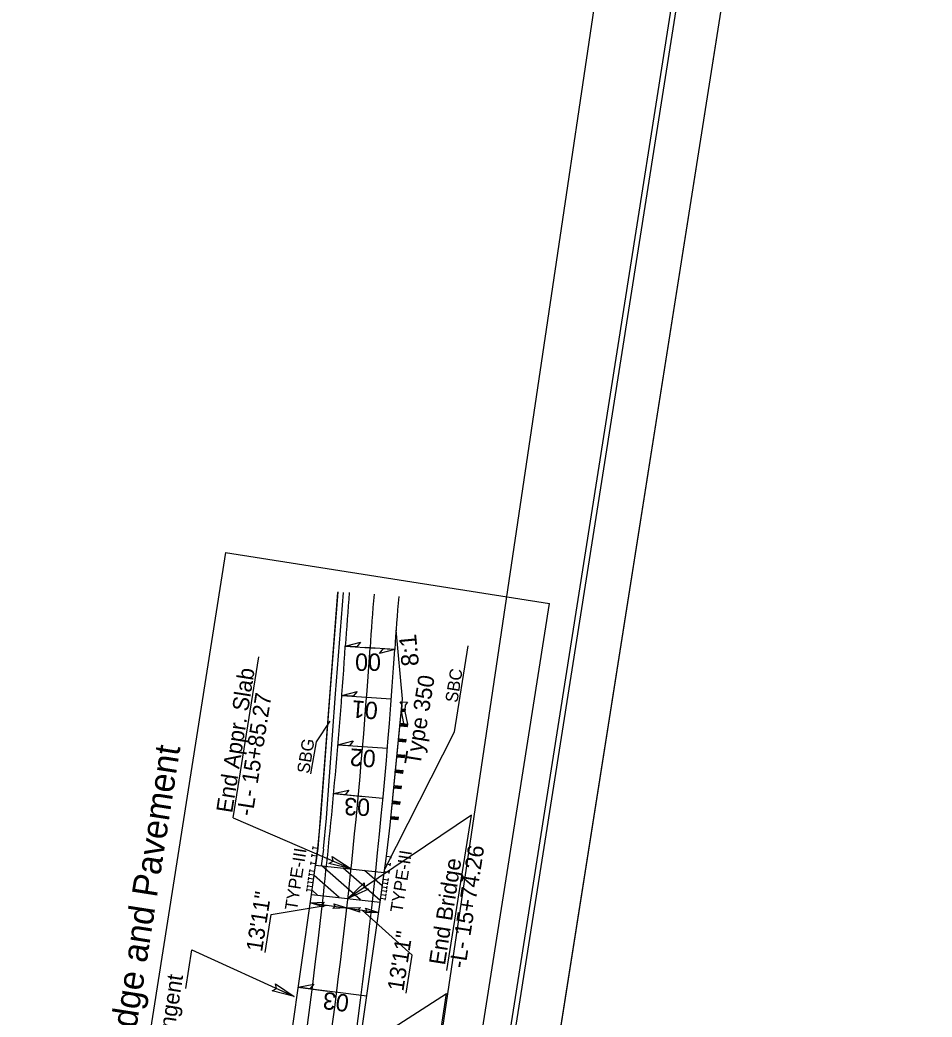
# Model space of a CAD drawing. Extents: x 1698669 to 1700017, y 707624 to 709955.
# Drawn here: x 1699557 to 1700017, y 708286 to 708790 of the extents above; entities that cross this region are included whole.
import ezdxf

# ---------------------------------------------------------------- set-up
doc = ezdxf.new("R2010")
doc.units = 0
for name, color, linetype in [('Prop Approach Slab', 7, 'Continuous'), ('Prop Approach Slab Hatching', 7, 'Continuous'), ('Prop Conc Shoulder Berm Gutter', 7, 'Continuous'), ('Prop Dimension', 7, 'Continuous'), ('Prop EOT', 7, 'Continuous'), ('Prop Guardrail', 7, 'Continuous'), ('Prop Guardrail Anchor Unit CELL', 7, 'Continuous'), ('Prop Horizontal Alignment', 7, 'Continuous'), ('Prop Paved Shoulder', 7, 'Continuous'), ('Prop Roadway Bridge', 7, 'Continuous'), ('Prop Structure Anchor Unit CELL', 7, 'Continuous'), ('Prop Superelevation  Arrow CELL', 7, 'Continuous'), ('Prop Superelevation Label', 7, 'Continuous'), ('Prop Terminator CELL', 7, 'Continuous'), ('Sheet Border Standard 30in CELL', 7, 'Continuous'), ('Sheet Clip Boundary CELL', 7, 'Continuous'), ('Sheet Cutting Line CELL', 7, 'Continuous'), ('Sheet Plot Border Inside CELL', 7, 'Continuous'), ('Sheet Plot Border Outside CELL', 7, 'Continuous')]:
    doc.layers.add(name, color=color, linetype=linetype)

msp = doc.modelspace()

# ---------------------------------------------------------------- linework, layer by layer
at = {"layer": 'Prop Approach Slab'}
for p, q in [((1699704.32, 708348.27), (1699706.42, 708363.04)), ((1699738.92, 708344.44), (1699741.04, 708359.38))]:
    msp.add_line(p, q, dxfattribs=at)
at = {"layer": 'Prop Approach Slab Hatching'}
for p, q in [((1699729.14, 708345.52), (1699709.52, 708362.71)), ((1699739.02, 708345.18), (1699720.31, 708361.57)), ((1699718.29, 708346.72), (1699705.67, 708357.78)), ((1699740.07, 708352.57), (1699731.09, 708360.43)), ((1699707.43, 708347.93), (1699704.62, 708350.39))]:
    msp.add_line(p, q, dxfattribs=at)
at = {"layer": 'Prop Conc Shoulder Berm Gutter'}
for p, q in [((1699713.71, 708449.74), (1699717.72, 708500.9)), ((1699709.06, 708387.08), (1699713.71, 708449.74)), ((1699707.61, 708371.48), (1699709.06, 708387.08)), ((1699707.61, 708371.48), (1699706.42, 708363.04)), ((1699741.04, 708359.38), (1699741.49, 708362.58))]:
    msp.add_line(p, q, dxfattribs=at)
at = {"layer": 'Prop Dimension'}
for p, q in [((1699776.52, 708430.34), (1699783.37, 708473.73)), ((1699664.9, 708386.89), (1699677.7, 708468.16)), ((1699706.82, 708425.3), (1699713.71, 708435.77)), ((1699741.29, 708360.98), (1699776.52, 708430.34)), ((1699703.98, 708409.06), (1699706.82, 708425.3)), ((1699664.9, 708386.89), (1699724.29, 708361.15)), ((1699785.02, 708388.28), (1699722.68, 708346.24)), ((1699772.67, 708309.84), (1699785.02, 708388.28)), ((1699684, 708338.22), (1699712.17, 708342.86)), ((1699703.73, 708344.06), (1699738.17, 708339.18)), ((1699680.98, 708318.99), (1699684, 708338.22)), ((1699755.18, 708317.69), (1699729.98, 708340.34)), ((1699640.89, 708300.84), (1699643.95, 708320.3)), ((1699643.95, 708320.3), (1699695.65, 708296.84)), ((1699752.15, 708298.46), (1699755.18, 708317.69)), ((1699711.72, 708259.43), (1699772.5, 708298.31)), ((1699763.45, 708240.74), (1699772.5, 708298.31))]:
    msp.add_line(p, q, dxfattribs=at)
at = {"layer": 'Prop EOT'}
for centre, radius, start, end in [((1701480.04, 708357.02), 1762.5, 175.32699, 176.20849), ((1701480.04, 708357.02), 1737.5, 175.32699, 176.20849), ((1696875.02, 708661), 2852.55, 353.61848, 356.23256), ((1696865.17, 708662.86), 2887.5, 350.26654, 356.20849), ((1696875.02, 708661), 2852.55, 346.9592, 353.61848)]:
    msp.add_arc(centre, radius, start, end, dxfattribs=at)
at = {"layer": 'Prop Guardrail'}
for p, q in [((1699717.47, 708500.55), (1699707.61, 708371.48)), ((1699742.21, 708367.64), (1699743.98, 708383.22))]:
    msp.add_line(p, q, dxfattribs=at)
at = {"layer": 'Prop Guardrail Anchor Unit CELL'}
for p, q in [((1699743.98, 708383.22), (1699749.76, 708441.37)), ((1699750.07, 708443.95), (1699749.12, 708445.5)), ((1699749.12, 708445.5), (1699752.78, 708445.21)), ((1699751.69, 708441.8), (1699749.7, 708440.75)), ((1699749.83, 708441.99), (1699751.69, 708441.8)), ((1699749.83, 708441.99), (1699751.57, 708440.56)), ((1699749.86, 708441.4), (1699750.07, 708443.95)), ((1699750.62, 708441.34), (1699749.86, 708441.4)), ((1699751.38, 708441.27), (1699750.62, 708441.34)), ((1699751.59, 708443.82), (1699751.38, 708441.27)), ((1699751.57, 708440.56), (1699751.69, 708441.8)), ((1699751.57, 708440.56), (1699751.63, 708441.18)), ((1699752.78, 708445.21), (1699751.59, 708443.82)), ((1699749.7, 708440.75), (1699751.57, 708440.56)), ((1699751, 708434.46), (1699749.7, 708440.75)), ((1699752.91, 708434.27), (1699751.57, 708440.56)), ((1699748.97, 708433.41), (1699751, 708434.46)), ((1699748.97, 708433.41), (1699752.78, 708433.03)), ((1699749.1, 708434.65), (1699752.91, 708434.27)), ((1699750.88, 708433.22), (1699749.1, 708434.65)), ((1699750.88, 708433.22), (1699751, 708434.46)), ((1699752.91, 708434.27), (1699750.88, 708433.22)), ((1699751, 708434.46), (1699752.78, 708433.03)), ((1699752.78, 708433.03), (1699752.91, 708434.27)), ((1699748.19, 708425.57), (1699750.18, 708426.63)), ((1699748.32, 708426.81), (1699752.05, 708426.44)), ((1699750.06, 708425.38), (1699748.32, 708426.81)), ((1699750.06, 708425.38), (1699750.18, 708426.63)), ((1699752.05, 708426.44), (1699750.06, 708425.38)), ((1699750.18, 708426.63), (1699751.92, 708425.2)), ((1699751.92, 708425.2), (1699752.05, 708426.44)), ((1699748.19, 708425.57), (1699751.92, 708425.2)), ((1699747.41, 708417.73), (1699749.49, 708418.78)), ((1699747.41, 708417.73), (1699751.31, 708417.34)), ((1699747.54, 708418.97), (1699751.44, 708418.59)), ((1699749.36, 708417.54), (1699747.54, 708418.97)), ((1699749.36, 708417.54), (1699749.49, 708418.78)), ((1699751.44, 708418.59), (1699749.36, 708417.54)), ((1699749.49, 708418.78), (1699751.31, 708417.34)), ((1699751.31, 708417.34), (1699751.44, 708418.59)), ((1699746.63, 708409.89), (1699746.76, 708411.14)), ((1699746.76, 708411.14), (1699750.53, 708410.76)), ((1699748.52, 708409.7), (1699746.76, 708411.14)), ((1699746.63, 708409.89), (1699748.64, 708410.95)), ((1699746.63, 708409.89), (1699750.41, 708409.52)), ((1699748.52, 708409.7), (1699748.64, 708410.95)), ((1699750.53, 708410.76), (1699748.52, 708409.7)), ((1699748.64, 708410.95), (1699750.41, 708409.52)), ((1699750.41, 708409.52), (1699750.53, 708410.76)), ((1699745.85, 708402.05), (1699747.87, 708403.11)), ((1699745.85, 708402.05), (1699749.64, 708401.68)), ((1699745.98, 708403.3), (1699749.77, 708402.92)), ((1699747.75, 708401.87), (1699745.98, 708403.3)), ((1699747.75, 708401.87), (1699747.87, 708403.11)), ((1699749.77, 708402.92), (1699747.75, 708401.87)), ((1699747.87, 708403.11), (1699749.64, 708401.68)), ((1699749.64, 708401.68), (1699749.77, 708402.92)), ((1699745.07, 708394.22), (1699747.09, 708395.27)), ((1699745.07, 708394.22), (1699748.87, 708393.84)), ((1699745.2, 708395.46), (1699748.99, 708395.08)), ((1699746.97, 708394.03), (1699745.2, 708395.46)), ((1699746.97, 708394.03), (1699747.09, 708395.27)), ((1699748.99, 708395.08), (1699746.97, 708394.03)), ((1699747.09, 708395.27), (1699748.87, 708393.84)), ((1699748.87, 708393.84), (1699748.99, 708395.08)), ((1699744.29, 708386.38), (1699744.42, 708387.62)), ((1699746.28, 708387.44), (1699744.29, 708386.38)), ((1699744.29, 708386.38), (1699748.02, 708386.01)), ((1699744.42, 708387.62), (1699748.15, 708387.25)), ((1699744.42, 708387.62), (1699746.28, 708387.44)), ((1699746.16, 708386.19), (1699744.42, 708387.62)), ((1699746.16, 708386.19), (1699746.28, 708387.44)), ((1699748.15, 708387.25), (1699746.16, 708386.19)), ((1699746.28, 708387.44), (1699748.02, 708386.01)), ((1699748.02, 708386.01), (1699748.15, 708387.25))]:
    msp.add_line(p, q, dxfattribs=at)
at = {"layer": 'Prop Horizontal Alignment'}
for p, q in [((1699660.94, 708520.75), (1699581.95, 708018.92)), ((1699660.94, 708520.75), (1699824.35, 708495.03)), ((1699745.36, 707993.2), (1699824.35, 708495.03))]:
    msp.add_line(p, q, dxfattribs=at)
for centre, radius, start, end in [((1701492.52, 708356.2), 1762.5, 175.32699, 176.20849), ((1696865.17, 708662.86), 2875, 346.96755, 356.20849)]:
    msp.add_arc(centre, radius, start, end, dxfattribs=at)
at = {"layer": 'Prop Paved Shoulder'}
for p, q in [((1699716.51, 708449.52), (1699720.51, 708500.68)), ((1699750.32, 708446.96), (1699747.02, 708481.61)), ((1699711.86, 708386.88), (1699716.51, 708449.54)), ((1699743.98, 708383.22), (1699750.32, 708446.96)), ((1699710.4, 708371.22), (1699711.85, 708386.82)), ((1699742.21, 708367.64), (1699743.98, 708383.22)), ((1699710.39, 708371.08), (1699709.19, 708362.64)), ((1699741.49, 708362.58), (1699742.21, 708367.64))]:
    msp.add_line(p, q, dxfattribs=at)
at = {"layer": 'Prop Roadway Bridge'}
for p, q in [((1699706.42, 708363.04), (1699741.04, 708359.38)), ((1699679.93, 708176.14), (1699704.32, 708348.27)), ((1699704.32, 708348.27), (1699738.92, 708344.44)), ((1699714.23, 708170.21), (1699738.92, 708344.44))]:
    msp.add_line(p, q, dxfattribs=at)
at = {"layer": 'Prop Structure Anchor Unit CELL'}
for p, q in [((1699704.32, 708348.27), (1699707.61, 708371.48)), ((1699705.04, 708371.12), (1699705.24, 708372.54)), ((1699707.61, 708371.48), (1699705.14, 708371.83)), ((1699704.49, 708367.25), (1699704.69, 708368.67)), ((1699707.06, 708367.61), (1699704.59, 708367.96)), ((1699738.92, 708344.44), (1699742.21, 708367.64)), ((1699742.21, 708367.64), (1699744.68, 708367.29)), ((1699744.58, 708366.58), (1699744.78, 708368)), ((1699703.39, 708359.52), (1699703.59, 708360.93)), ((1699703.94, 708363.38), (1699704.14, 708364.8)), ((1699706.52, 708363.74), (1699704.04, 708364.09)), ((1699741.66, 708363.78), (1699744.13, 708363.43)), ((1699744.03, 708362.72), (1699744.23, 708364.13)), ((1699702.84, 708355.65), (1699703.04, 708357.07)), ((1699705.42, 708356.01), (1699702.94, 708356.36)), ((1699703.12, 708357.58), (1699703.32, 708359)), ((1699705.69, 708357.94), (1699703.22, 708358.29)), ((1699705.97, 708359.87), (1699703.49, 708360.23)), ((1699740.56, 708356.04), (1699743.04, 708355.69)), ((1699741.11, 708359.91), (1699743.59, 708359.56)), ((1699742.94, 708354.98), (1699743.14, 708356.4)), ((1699743.49, 708358.85), (1699743.69, 708360.27)), ((1699702.02, 708349.85), (1699702.22, 708351.27)), ((1699702.3, 708351.78), (1699702.5, 708353.2)), ((1699704.87, 708352.14), (1699702.4, 708352.49)), ((1699702.57, 708353.72), (1699702.77, 708355.13)), ((1699705.14, 708354.07), (1699702.67, 708354.42)), ((1699740.01, 708352.17), (1699742.49, 708351.82)), ((1699740.29, 708354.11), (1699742.76, 708353.76)), ((1699742.12, 708349.18), (1699742.32, 708350.6)), ((1699742.39, 708351.11), (1699742.59, 708352.53)), ((1699742.66, 708353.05), (1699742.86, 708354.47)), ((1699704.6, 708350.21), (1699702.12, 708350.56)), ((1699739.19, 708346.37), (1699741.67, 708346.02)), ((1699739.47, 708348.31), (1699741.94, 708347.96)), ((1699739.74, 708350.24), (1699742.22, 708349.89)), ((1699741.57, 708345.31), (1699741.77, 708346.73)), ((1699741.84, 708347.25), (1699742.04, 708348.66))]:
    msp.add_line(p, q, dxfattribs=at)
at = {"layer": 'Prop Superelevation  Arrow CELL'}
for p, q in [((1699721.4, 708473.59), (1699736.37, 708472.57)), ((1699746.34, 708471.89), (1699731.38, 708472.91)), ((1699719.65, 708448.65), (1699734.62, 708447.64)), ((1699717.68, 708423.73), (1699732.65, 708422.71)), ((1699715.52, 708399.14), (1699730.46, 708397.76)), ((1699697.69, 708301.44), (1699712.56, 708299.54))]:
    msp.add_line(p, q, dxfattribs=at)
for points in [[(1699721.4, 708473.59), (1699729.06, 708475.58), (1699727.17, 708473.2)], [(1699746.34, 708471.89), (1699738.69, 708469.91), (1699740.58, 708472.29)], [(1699719.65, 708448.65), (1699727.3, 708450.64), (1699725.42, 708448.26)], [(1699717.68, 708423.73), (1699725.33, 708425.72), (1699723.45, 708423.34)], [(1699715.52, 708399.14), (1699723.22, 708400.94), (1699721.28, 708398.61)], [(1699697.69, 708301.44), (1699705.44, 708302.97), (1699703.42, 708300.71)]]:
    msp.add_lwpolyline(points, close=True, dxfattribs=at)
at = {"layer": 'Prop Superelevation Label'}
for p, q in [((1699719.65, 708448.65), (1699744.58, 708446.96)), ((1699717.68, 708423.73), (1699742.61, 708422.03)), ((1699715.52, 708399.14), (1699740.39, 708396.84)), ((1699697.69, 708301.44), (1699732.2, 708297.03))]:
    msp.add_line(p, q, dxfattribs=at)
at = {"layer": 'Prop Terminator CELL'}
for points in [[(1699714.74, 708367.41), (1699724.29, 708361.15), (1699713.12, 708363.82), (1699715.23, 708365.08)], [(1699733.07, 708350.91), (1699722.66, 708346.22), (1699730.91, 708354.21), (1699730.84, 708351.75)], [(1699710.33, 708341.95), (1699703.73, 708344.06), (1699710.7, 708344.31), (1699709.67, 708343.23)], [(1699715.54, 708343.58), (1699722.14, 708341.45), (1699715.17, 708341.21), (1699716.2, 708342.29)], [(1699728.75, 708339.33), (1699722.14, 708341.45), (1699729.12, 708341.7), (1699728.09, 708340.62)], [(1699731.57, 708341.31), (1699738.17, 708339.18), (1699731.2, 708338.94), (1699732.23, 708340.02)], [(1699686.17, 708303.2), (1699695.65, 708296.84), (1699684.51, 708299.64), (1699686.63, 708300.87)]]:
    msp.add_lwpolyline(points, close=True, dxfattribs=at)
at = {"layer": 'Sheet Border Standard 30in CELL'}
msp.add_lwpolyline([(1698952.79, 709620.82), (1698719.55, 708139.06), (1699756.78, 707975.8), (1699990.01, 709457.55)], close=True, dxfattribs=at)
at = {"layer": 'Sheet Clip Boundary CELL'}
msp.add_lwpolyline([(1698758.74, 708183.76), (1698948.48, 709389.16), (1699099.99, 709375.69), (1699125.7, 709552.26), (1699940.11, 709424.07), (1699732.55, 708026.32)], close=True, dxfattribs=at)
at = {"layer": 'Sheet Cutting Line CELL'}
msp.add_line((1699755.5, 707806.94), (1700017.35, 709470.46), dxfattribs=at)
at = {"layer": 'Sheet Plot Border Inside CELL'}
msp.add_lwpolyline([(1698952.21, 709633.56), (1698693.08, 707987.33), (1699735.35, 707823.27), (1699994.48, 709469.5)], close=True, dxfattribs=at)
at = {"layer": 'Sheet Plot Border Outside CELL'}
msp.add_lwpolyline([(1698930.73, 709641.5), (1698668.88, 707977.98), (1699755.5, 707806.94), (1700017.35, 709470.46)], close=True, dxfattribs=at)

# ---------------------------------------------------------------- texts
at = {"layer": 'Prop Dimension'}
for s, height, rotation, p in [('8:1', 8.75, 95.4468, (1699758.59, 708463.82)), ('End Appr. Slab', 8.2031, 81.1024, (1699664.34, 708389.07)), ('Type 350', 8.203, 80.7477, (1699759.22, 708413.07)), ('-L- 15+85.27', 8.2031, 81.1024, (1699674.61, 708387.46)), ('Relationship Between Bridge and Pavement', 12.8174, 81.1024, (1699586.34, 708091.22)), ('-L- 15+74.26', 8.2031, 81.1024, (1699781.91, 708310.68)), ('End Bridge', 8.203, 81.1024, (1699771.64, 708312.29)), ('13\'11"', 8.203, 81.1024, (1699679.38, 708318.99)), ('13\'11"', 8.203, 81.1024, (1699750.65, 708299.09)), ('Bridge on Tangent', 8.2031, 81.1024, (1699625.66, 708218.1))]:
    msp.add_text(s, height=height, rotation=rotation, dxfattribs=at).set_placement(p)
at = {"layer": 'Prop Structure Anchor Unit CELL'}
for s, p in [('SBC', (1699777.93, 708444.75)), ('SBG', (1699703.17, 708408.98)), ('TYPE-III', (1699697, 708339.96)), ('TYPE-III', (1699750.15, 708338.83))]:
    msp.add_text(s, height=6.25, rotation=81.0546, dxfattribs=at).set_placement(p)
at = {"layer": 'Prop Superelevation Label'}
msp.add_text('00', height=8.75, dxfattribs=at).set_placement((1699726.35, 708461.08))
for s, rotation, p in [('01', 175.6067, (1699738.1, 708445.26)), ('02', 175.6067, (1699737.05, 708420.99)), ('03', 177.7543, (1699734.06, 708396.54)), ('03', 172.7286, (1699723.67, 708297.57))]:
    msp.add_text(s, height=8.75, rotation=rotation, dxfattribs=at).set_placement(p)

doc.saveas('drawing.dxf')
